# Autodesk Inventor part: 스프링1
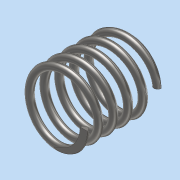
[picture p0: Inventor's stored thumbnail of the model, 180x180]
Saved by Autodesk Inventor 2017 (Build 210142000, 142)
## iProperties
Part Number: 스프링1
Material: 스테인레스 스틸
Document SubType Name: Modeling
Designer: MRC
Density: 8 g/cm^3
Appearance: 반연마
Mass: 6.57569 g
Surface Area: 16.7185 cm^2
Volume: 0.821961 cm^3
Author: MRC
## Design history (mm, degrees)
sketch "스케치1"
  geometry: L1 (0, 0)-(0, 20.5); L2 (0, 0)-(8.5, 0); L3 (0, 20.5)-(8.5, 20.5); C1 r 1 at (8.5, 0)
  constraints: 6 end point, 2 horizontal, 1 centre point, 1 coincident, 1 parallel, 1 vertical
  dimensions: "d0" = 20.5 distance of L1.start L1.end (derived); "d1" = 17 diameter of L2.end L1; "d2" = 2 diameter of C1
feature "코일1" sketch "스케치1" pitch "d3" = 10; turns "d5" = 5; dims "d4" = 20.5 (= d0), "d6" = 0, angle "d7" = 90 deg, angle "d8" = 90 deg, "d9" = 0, "d10" = 0
sketch "스케치2"
  geometry: L1 (20.5, 14.331)-(0, 14.331); L2 (0, 14.331)-(0, -14.331); L3 (0, -14.331)-(20.5, -14.331); L4 (20.5, -14.331)-(20.5, 14.331); 2 further points
  constraints: 8 end point, 2 parallel, 1 coincident, 1 horizontal, 1 midpoint, 1 perpendicular
  dimensions: "d11" = 28.66142 distance of L3.end L1.start; "d12" = 20.5 distance of L2.end L3.end (= d0)
extrude "돌출1" sketch "스케치2" stored distance "d13" = 0; taper "d14" = 0 deg
node "솔리드1"
